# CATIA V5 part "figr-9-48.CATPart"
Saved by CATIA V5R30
Part number: Part1
Bounding box of the stored display mesh (mm): x -53.419 to 50, y -50 to 50, z -57.709 to 133.109
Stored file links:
  D:\PROJECTS\CATIA V56R 2020\Resources\Parts File\c09_catia_v5_6r2020_prt\figr-9-48.CATPart
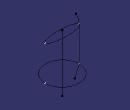
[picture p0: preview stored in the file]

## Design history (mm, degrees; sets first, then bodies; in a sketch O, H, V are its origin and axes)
Body1 (main body)
  Plane1: type Offset, RefPlane xy-plane, Offset 103
  Sketch1 on Plane1, origin (0, 0, 103), H (1, 0, 0), V (0, 1, 0)
    ellipse A1 centre (0, 0) semi-axes 50, 13.2069 rotation 0
    point P1 (50, 0)
    "Radius" A1 = 50
    coincidence: P1 H, A1 P1
  Extremum1: Reference Sketch1, Direction (1, 2, 3)
  Sketch2 on xy-plane, origin (0, 0, 0), H (1, 0, 0), V (0, 1, 0)
    circle A1 centre (0, 0) radius 50
    radius A1 = 50
  Extremum2: Reference Sketch2, Direction (1, 2, 3)
  Sketch3 on zx-plane, origin (0, 0, 0), H (-1, 0, 0), V (0, 0, 1)
    spline S1 through (37.7591, -31.0289) (41.8235, -21.251) (50, 0) (49.8084, 85.7657) (50, 103) (41.6255, 133.1089)
    reference projected line E1 (-50, 103) -> (50, 103) from Sketch1.A1
    point P1 (50, 0)
    point P2 (50, 103)
    distance V P1 = 50
    distance P2 V = 50
    coincidence: P1 H, P2 E1
  Sketch4 on zx-plane, origin (0, 0, 0), H (-1, 0, 0), V (0, 0, 1)
    line L1 (0, 111.062) -> (0, -57.7094)
    point P1 (0, 111.062)
    coincidence: P1 V
    vertical: L1 V
  Loft1: solid, Sections (Sketch1; Sketch2), Spine Sketch4, Guides Sketch3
